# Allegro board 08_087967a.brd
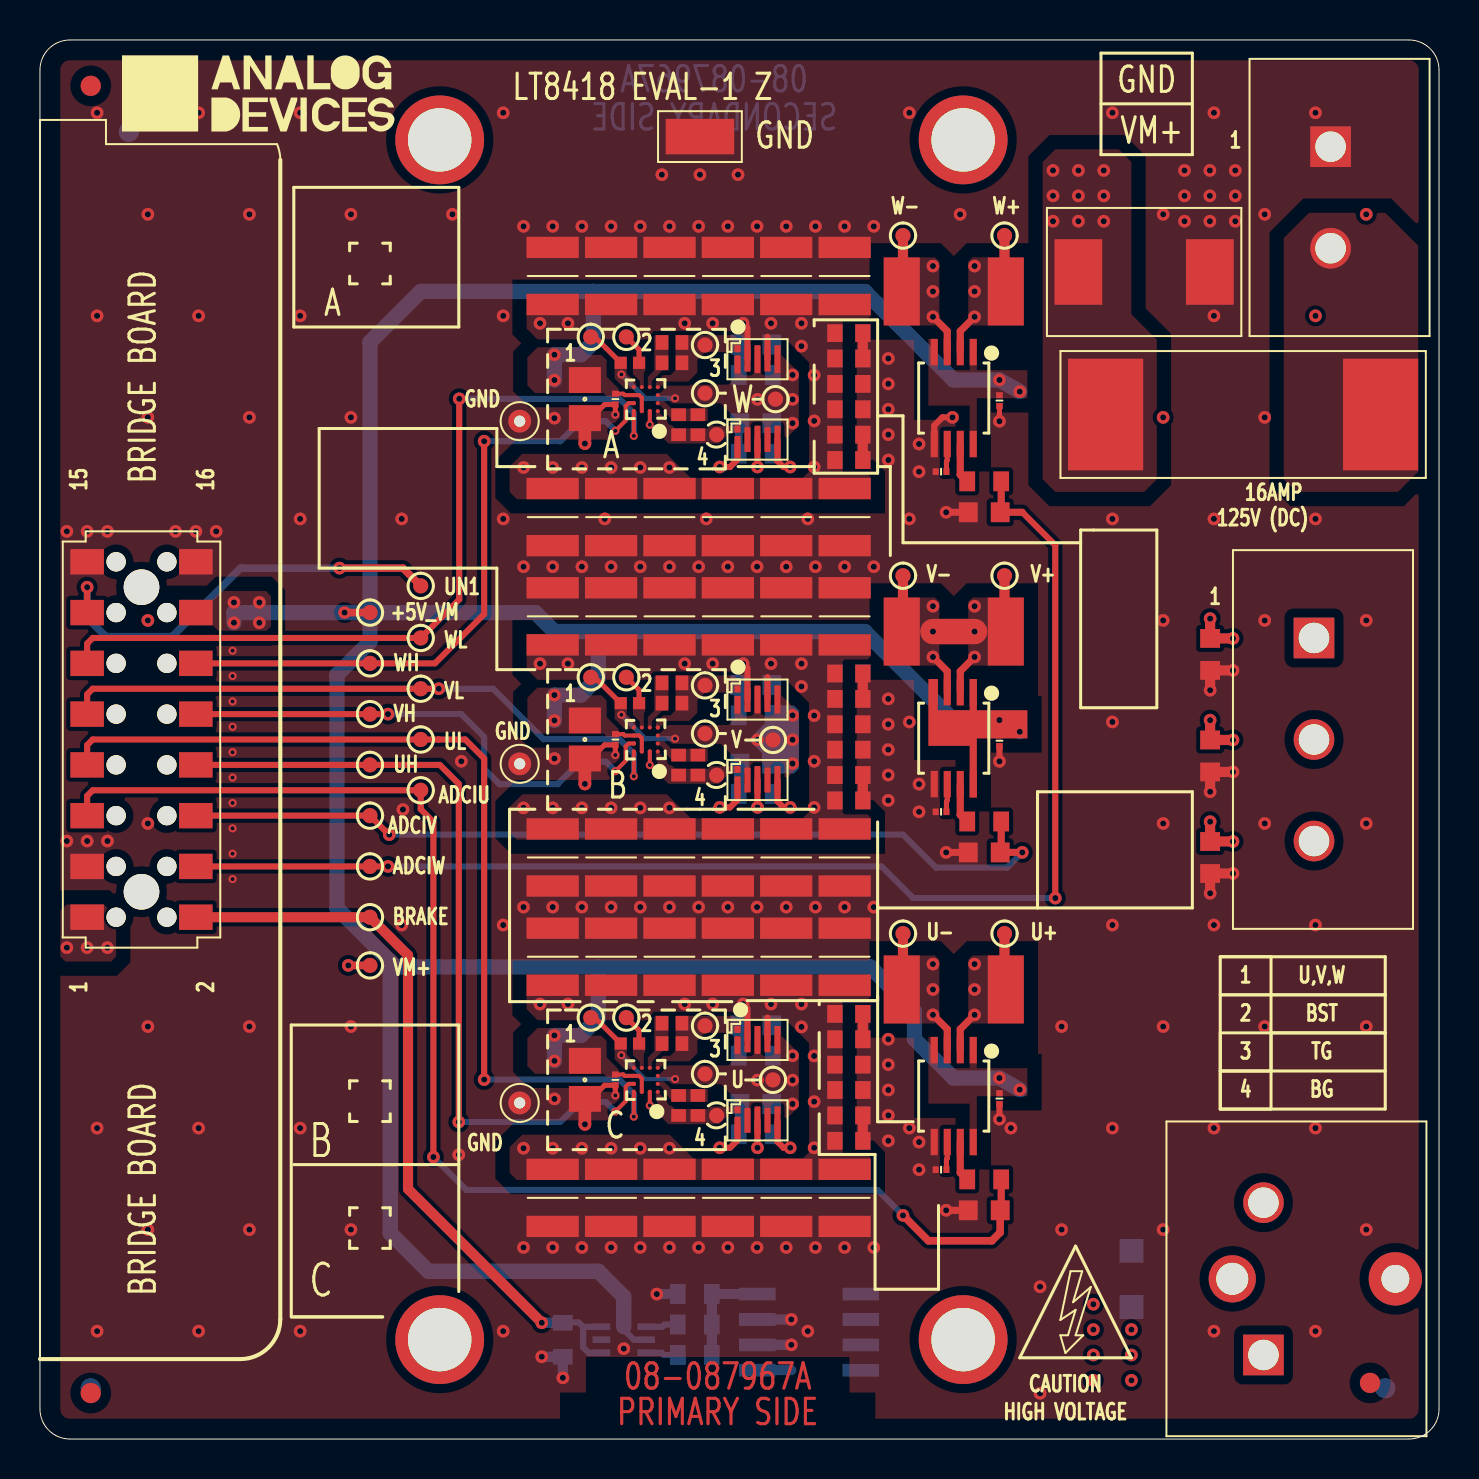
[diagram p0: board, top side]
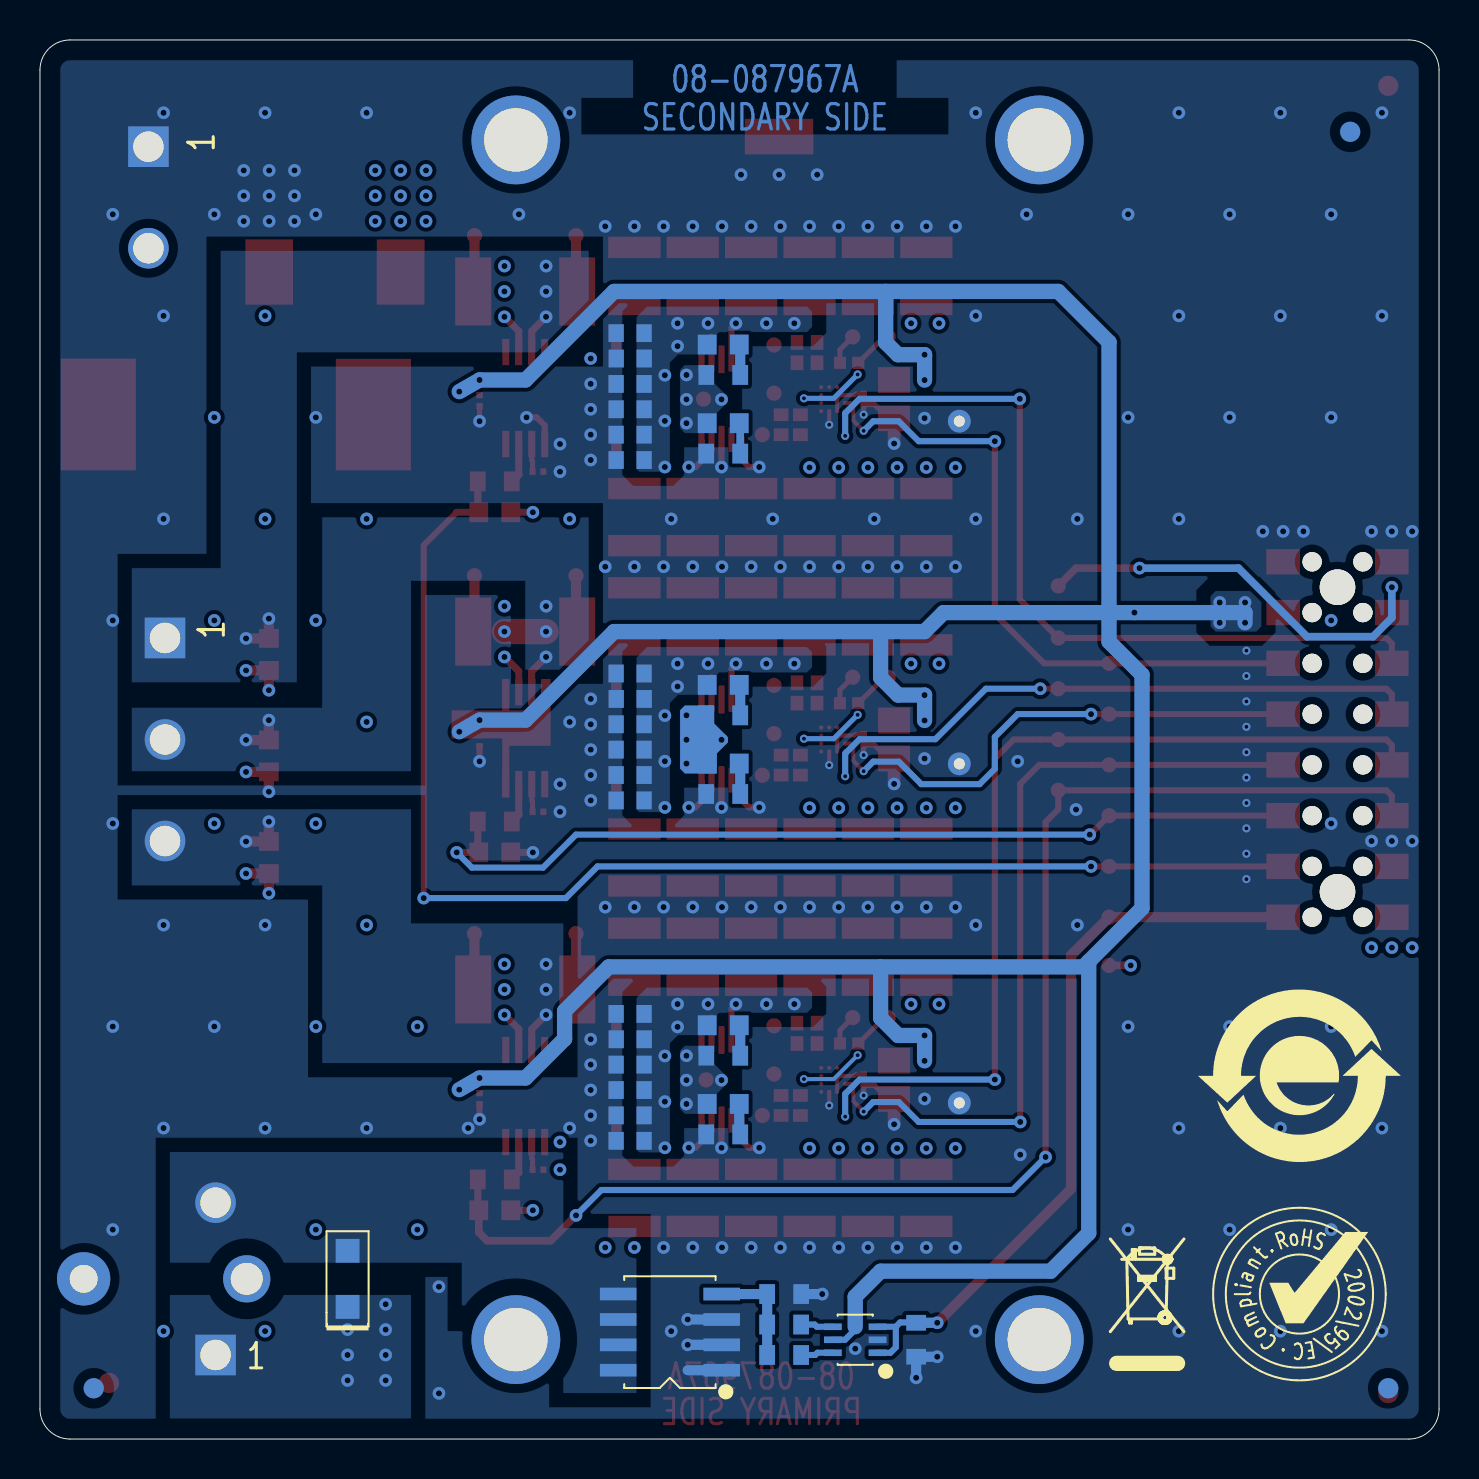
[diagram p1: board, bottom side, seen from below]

Outline 70 x 70 mm; copper layers: TOP, L2_GND, L3_SIG, BOTTOM. Coordinates in mm from the lower left corner of the outline.
Outline path: 0,68.5 arc(0.44,69.56) 1.5,70 68.5,70 arc(69.56,69.56) 70,68.5 70,1.5 arc(69.56,0.44) 68.5,0 1.5,0 arc(0.44,0.44) 0,1.5 0,68.5

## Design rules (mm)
constraint set DEFAULT: min track width 0.203
net group ADC_I_U: nets _N51 ADC_I_U
net group ADC_I_V: nets _N52 ADC_I_V
net group ADC_I_W: nets _N55 ADC_I_W
net group U: nets _N126 _N127
net group V: nets _N129 _N130
net group W: nets _N131 _N132
net group _N123: nets _N123 _N147 _N148

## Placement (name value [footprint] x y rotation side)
C1  4.7uF  [C1210H87]  28.57 58.19 90 top
C2  4.7uF  [C1210H87]  37.34 46.13 270 top
C3  4.7uF  [C0805H60]  27.26 35 90 top
C4  0.1uF  [C0201]  28.79 35 90 top
C5  0.1uF  [C0201]  28.79 52.03 90 top
C6  0.1uF  [C0402_B]  29.51 36.82 0 top
C7  0.1uF  [C0402_B]  29.51 19.79 0 top
C8  0.1uF  [C0402_B]  29.51 53.85 0 top
C9  0.1uF  [C0201]  45.09 13.48 180 top
C10  0.1uF  [C0201]  45.09 31.38 180 top
C11  0.1uF  [C0201]  45.09 48.4 180 top
C12  0.1uF  [C0201]  48.01 51.96 90 top
C13  0.1uF  [C0201]  48.01 34.94 90 top
C14  0.1uF  [C0201]  28.79 17.97 90 top
C15  4.7uF  [C0805H60]  27.26 17.97 90 top
C16  4.7uF  [C0805H60]  27.26 52.03 90 top
C17  0.1uF  [C0201]  48.01 17.03 90 top
C18  4.7uF  [C1210H87]  34.42 58.19 90 top
C19  4.7uF  [C1210H87]  37.34 58.19 90 top
C20  4.7uF  [C1210H87]  25.65 58.19 90 top
C21  4.7uF  [C1210H87]  34.42 46.13 270 top
C22  4.7uF  [C1210H87]  40.26 46.13 270 top
C23  4.7uF  [C1210H87]  28.57 46.13 270 top
C24  4.7uF  [C1210H87]  31.5 58.19 90 top
C25  4.7uF  [C1210H87]  31.5 46.13 270 top
C26  4.7uF  [C1210H87]  34.42 41.16 90 top
C27  4.7uF  [C1210H87]  40.26 29.1 270 top
C28  4.7uF  [C1210H87]  34.42 29.1 270 top
C29  4.7uF  [C1210H87]  31.5 41.16 90 top
C30  4.7uF  [C1210H87]  28.57 41.16 90 top
C31  4.7uF  [C1210H87]  28.57 29.1 270 top
C32  4.7uF  [C1210H87]  25.65 41.16 90 top
C33  4.7uF  [C1210H87]  25.65 29.1 270 top
C34  4.7uF  [C1210H87]  31.5 12.07 270 top
C35  4.7uF  [C1210H87]  28.57 12.07 270 top
C36  4.7uF  [C1210H87]  25.65 12.07 270 top
C37  4.7uF  [C1210H87]  37.34 24.13 90 top
C38  4.7uF  [C1210H87]  25.65 24.13 90 top
C39  4.7uF  [C1210H87]  40.26 24.13 90 top
C40  4.7uF  [C1210H87]  40.26 12.07 270 top
C41  4.7uF  [C1210H87]  34.42 12.07 270 top
C42  4.7uF  [C1210H87]  25.65 46.13 270 top
C43  4.7uF  [C1210H87]  40.26 41.16 90 top
C44  4.7uF  [C1210H87]  37.34 41.16 90 top
C45  4.7uF  [C1210H87]  37.34 29.1 270 top
C46  4.7uF  [C1210H87]  37.34 12.07 270 top
C47  4.7uF  [C1210H87]  34.42 24.13 90 top
C48  4.7uF  [C1210H87]  28.57 24.13 90 top
C49  4.7uF  [C1210H87]  31.5 29.1 270 top
C50  4.7uF  [C1210H87]  31.5 24.13 90 top
C51  4.7uF  [C1210H87]  40.26 58.19 90 top
C52  47NF  [C0603]  40.47 20 0 top
C53  47NF  [C0603]  40.47 17.46 0 top
C54  47NF  [C0603]  40.47 18.73 0 top
C55  47NF  [C0603]  40.47 21.27 0 top
C56  47NF  [C0603]  40.47 14.92 0 top
C57  47NF  [C0603]  40.47 16.19 0 top
C58  0.22UF  [C0603]  40.47 51.52 0 bottom
C59  0.22UF  [C0603]  40.47 52.79 0 bottom
C60  0.22UF  [C0603]  40.47 50.25 0 bottom
C61  0.22UF  [C0603]  40.47 48.98 0 bottom
C62  0.22UF  [C0603]  40.47 54.06 0 bottom
C63  0.22UF  [C0603]  40.47 55.33 0 bottom
C64  47NF  [C0603]  40.47 34.49 0 top
C65  47NF  [C0603]  40.47 35.76 0 top
C66  47NF  [C0603]  40.47 31.95 0 top
C67  47NF  [C0603]  40.47 37.03 0 top
C68  47NF  [C0603]  40.47 38.3 0 top
C69  47NF  [C0603]  40.47 33.22 0 top
C70  0.22UF  [C0603]  40.47 35.76 0 bottom
C71  0.22UF  [C0603]  40.47 38.3 0 bottom
C72  0.22UF  [C0603]  40.47 37.03 0 bottom
C73  0.22UF  [C0603]  40.47 34.49 0 bottom
C74  0.22UF  [C0603]  40.47 33.22 0 bottom
C75  0.22UF  [C0603]  40.47 31.95 0 bottom
C76  47NF  [C0603]  40.47 48.98 0 top
C77  47NF  [C0603]  40.47 55.33 0 top
C78  47NF  [C0603]  40.47 54.06 0 top
C79  47NF  [C0603]  40.47 52.79 0 top
C80  47NF  [C0603]  40.47 51.52 0 top
C81  47NF  [C0603]  40.47 50.25 0 top
C82  0.22UF  [C0603]  40.47 18.73 0 bottom
C83  0.22UF  [C0603]  40.47 21.27 0 bottom
C84  0.22UF  [C0603]  40.47 17.46 0 bottom
C85  0.22UF  [C0603]  40.47 16.19 0 bottom
C86  0.22UF  [C0603]  40.47 14.92 0 bottom
C87  0.22UF  [C0603]  40.47 20 0 bottom
C88  2200pF  [C0603#2]  47.24 46.37 180 top
C89  2200pF  [C0603#2]  47.24 29.35 180 top
C90  2200pF  [C0603#2]  47.24 11.44 180 top
C91  1000pF  [C0603#2]  58.55 29.1 270 top
C92  1000pF  [C0603#2]  58.55 34.18 270 top
C93  1000pF  [C0603#2]  58.55 39.26 270 top
C94  0.01uF  [C0603#2]  35.81 16.77 180 bottom
C95  0.01uF  [C0603#2]  35.81 20.7 180 bottom
C96  0.01uF  [C0603#2]  35.81 33.8 180 bottom
C97  0.01uF  [C0603#2]  35.81 37.73 180 bottom
C98  0.01uF  [C0603#2]  35.81 50.83 180 bottom
C99  0.01uF  [C0603#2]  35.81 54.76 180 bottom
D1  PMEG10020AELRX  [SOD123F]  54.61 8.01 90 bottom
D2  SMCJ58CA  [DO214AB_A]  55.24 58.39 180 top
F1  16A  [FSML606W211H211]  60.2 51.26 0 top
NOREF  -  [unnamed]  2.54 2.3 0 top
NOREF#2  -  [#2]  70 70 180 top
NOREF#3  -  [#2]  -69.85 -54.85 0 top
NOREF#4  -  [#2]  -69.85 -54.85 0 top
NOREF#5  -  [unnamed]  46.19 4.97 0 top
NOREF#6  -  [#2]  10.8 67.32 0 top
NOREF#7  -  [unnamed]  46.19 65 0 top
NOREF#8  -  [unnamed]  2.54 67.7 0 top
NOREF#9  -  [#2]  0 70 270 top
NOREF#10  -  [#2]  0 0 0 top
NOREF#11  -  [unnamed]  20 65 0 top
NOREF#12  -  [#2]  68.5 0 90 top
NOREF#13  -  [#2]  0 68.5 0 top
NOREF#14  -  [unnamed]  20 4.97 0 top
NOREF#15  -  [#2]  0 0 0 top
NOREF#16  -  [unnamed]  66.55 2.81 0 top
NOREF#17  -  [#2]  70 1.5 0 top
NOREF#18  -  [#2]  70 0 90 top
NOREF#19  -  [#2]  35 95.4 0 top
NOREF#20  -  [#2]  120.9 264.92 0 top
NOREF#21  -  [#2]  231.78 215.66 0 top
NOREF#22  -  [#2]  -69.85 -54.85 0 top
NOREF#23  -  [#2]  0 0 0 top
NOREF#24  -  [#2]  1.5 70 0 top
NOREF#25  -  [unnamed]  2.54 2.54 180 bottom
NOREF#26  -  [#2]  6.99 7.25 180 bottom
NOREF#27  -  [unnamed]  67.31 2.54 180 bottom
NOREF#28  -  [#2]  14.81 3.47 180 bottom
NOREF#29  -  [unnamed]  4.45 65.41 180 bottom
NOREF#30  -  [#2]  6.99 18.17 180 bottom
P1  1838210000  [CNWEIDMULLER1838210000]  64.57 64.66 270 top
P2  1907131  [CNPHOENIX1907131]  61.21 4.2 90 top
P3  HLE-108-02-F-DV-BE-A-K-TR  [CNSMFHDR2X8L800W200H154]  5.08 35 90 top
P4  1838220000  [CNWEIDMULLER1838220000]  63.74 40.08 270 top
Q1  EPC2204  [DIE6_2_5X1_5]  35.9 54.03 0 top
Q2  EPC2204  [DIE6_2_5X1_5]  35.9 50 0 top
Q3  EPC2204  [DIE6_2_5X1_5]  35.9 37 0 top
Q4  EPC2204  [DIE6_2_5X1_5]  35.9 32.97 0 top
Q5  EPC2204  [DIE6_2_5X1_5]  35.9 19.97 0 top
Q6  EPC2204  [DIE6_2_5X1_5]  35.9 15.94 0 top
Q7  SI4190ADY-T1-GE3  [SO8NB-5]  38.48 5.35 90 bottom
R1  0.001  [R2512H31_PAD71X134]  45.72 57.42 0 top
R2  0.001  [R2512H31_PAD71X134]  45.72 22.49 0 top
R3  0.001  [R2512H31_PAD71X134]  45.72 40.4 0 top
R4  5.6  [R0402]  31.62 19.79 0 top
R5  5.6  [R0402]  31.62 20.8 0 top
R6  5.6  [R0402]  32.92 16.69 270 top
R7  5.6  [R0402]  31.95 16.69 270 top
R8  5.6  [R0402]  31.95 33.72 270 top
R9  5.6  [R0402]  32.92 33.72 270 top
R13  5.6  [R0402]  31.62 36.82 0 top
R14  5.6  [R0402]  31.62 37.83 0 top
R15  5.6  [R0402]  31.95 50.75 270 top
R16  5.6  [R0402]  32.92 50.75 270 top
R17  5.6  [R0402]  31.62 54.86 0 top
R18  5.6  [R0402]  31.62 53.85 0 top
R19  10K  [R0603]  26.16 4.97 270 bottom
R20  50  [R0603]  35.81 15.24 0 bottom
R21  50  [R0603]  35.81 19.18 0 bottom
R22  50  [R0603]  35.81 32.27 0 bottom
R23  50  [R0603]  35.81 36.21 0 bottom
R24  50  [R0603]  35.81 49.3 0 bottom
R25  50  [R0603]  35.81 53.24 0 bottom
R26  1K  [R0603]  32.77 4.2 0 bottom
R27  1K  [R0603]  32.77 5.73 0 bottom
R28  10K  [R0603]  32.77 7.25 180 bottom
R29  1K  [R0603]  47.24 12.99 0 top
R30  1K  [R0603]  47.24 47.92 0 top
R31  1K  [R0603]  47.24 30.9 0 top
TP1  TESTPAD  [TPSMC30]  29.34 55.14 0 top
TP2  TESTPAD  [TPSMC30]  29.34 38.11 0 top
TP3  TESTPAD  [TPSMC30]  29.34 21.08 0 top
TP4  TESTPAD  [TPSMC30]  33.27 37.71 0 top
TP5  TESTPAD  [TPSMC30]  33.27 20.68 0 top
TP6  TESTPAD  [TPSMC30]  33.27 54.74 0 top
TP7  TESTPAD  [TPSMC30]  36.67 17.97 0 top
TP8  TESTPAD  [TPSMC30]  27.56 21.08 0 top
TP9  TESTPAD  [TPSMC30]  36.67 34.98 0 top
TP10  TESTPAD  [TPSMC30]  27.56 38.11 0 top
TP11  TESTPAD  [TPSMC30]  36.8 52.03 0 top
TP12  TESTPAD  [TPSMC30]  27.56 55.14 0 top
TP13  TESTPAD  [TPSMC30]  33.86 50.25 0 top
TP14  TESTPAD  [TPSMC30]  33.86 33.21 0 top
TP15  TESTPAD  [TPSMC30]  33.86 16.19 0 top
TP19  TESTPAD  [TPSMC30]  33.27 52.32 0 top
TP20  TESTPAD  [TPSMC30]  33.27 35.29 0 top
TP21  TESTPAD  [TPSMC30]  33.27 18.26 0 top
TP22  TESTPAD  [TPSMC30]  19.05 35 0 top
TP23  TESTPAD  [TPSMC30]  16.51 33.73 0 top
TP24  TESTPAD  [TPSMC30]  19.05 37.54 0 top
TP25  TESTPAD  [TPSMC30]  16.51 36.27 0 top
TP26  TESTPAD  [TPSMC30]  19.05 40.08 0 top
TP27  TESTPAD  [TPSMC30]  16.51 38.81 0 top
TP28  TESTPAD  [TPSMC30]  43.18 43.19 0 top
TP29  TESTPAD  [TPSMC30]  48.26 43.19 0 top
TP30  TESTPAD  [TPSMC30]  43.18 60.21 0 top
TP31  TESTPAD  [TPSMC30]  48.26 60.21 0 top
TP32  TESTPAD  [TPSMC30]  43.18 25.29 0 top
TP33  TESTPAD  [TPSMC30]  48.26 25.29 0 top
TP34  TESTPAD  [TPSMC30]  16.51 26.11 0 top
TP35  TESTPAD  [TPSMC30]  16.51 28.65 0 top
TP36  TESTPAD  [TPSMC30]  16.51 31.19 0 top
TP37  TESTPAD  [TPSMC30]  19.05 32.46 0 top
TP38  TESTPAD  [TPSMC30]  19.05 42.69 0 top
TP39  TESTPAD  [TPSMC30]  16.51 41.35 0 top
TP40  TESTPAD  [TPSMC30]  16.51 23.7 0 top
TP41  5015  [CNKEY5015TP]  33.02 65.16 0 top
U1  LT8418ACBZ-R7  [WLCSP16_12P_1_67X1_67H0_56]  30.31 52.03 180 top
U2  LT8418ACBZ-R7  [WLCSP16_12P_1_67X1_67H0_56]  30.31 35 180 top
U3  LT8418ACBZ-R7  [WLCSP16_12P_1_67X1_67H0_56]  30.31 17.97 180 top
U4  LT1999HMS8-50#PBF  [MSOP8]  45.72 35.07 180 top
U5  LT1999HMS8-50#PBF  [MSOP8]  45.72 17.16 180 top
U6  LT1999HMS8-50#PBF  [MSOP8]  45.72 52.08 180 top
U7  74LVC2G17GW,125  [SOT363]  29.21 4.97 90 bottom
W1  WP22  [TPC45D22]  24 50.93 0 top
W2  WP22  [TPC45D22]  24 33.78 0 top
W3  WP22  [TPC45D22]  24 16.82 0 top

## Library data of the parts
C1 C2 C18-C51 = CAP: User Part Number: UPN; Tolerance: 10; alternate symbols: (C1210L); tolerance: 10
C3 C15 C16 = CAP: Tolerance: 10; User Part Number: UPN; alternate symbols: (C0805H60); tolerance: 10
C4 C5 C9-C14 C17 = CAP: Tolerance: 10; User Part Number: UPN; alternate symbols: (C0201L); tolerance: 10
C6-C8 = CAP: Tolerance: 10; User Part Number: UPN; alternate symbols: (C0402_BL); tolerance: 10
C52-C87 = CAP: User Part Number: UPN; Tolerance: 10; alternate symbols: (C0603L); tolerance: 10
C88-C90 C94-C99 = CAP: User Part Number: UPN; Tolerance: 10; alternate symbols: (C0603); tolerance: 10
C91-C93 = CAP: User Part Number: UPN; Tolerance: 5; alternate symbols: (C0603); tolerance: 5
D1 = DIOSCHOTTKY: Tolerance: N/A; User Part Number: UPN; alternate symbols: (SOD123F); tolerance: N/A
D2 = DIOZNR_V2: User Part Number: UPN; Tolerance: N/A; alternate symbols: (DO214AB_A); tolerance: N/A
F1 = FSFUSE: Tolerance: N/A; User Part Number: UPN; alternate symbols: (FSML606W211H211); tolerance: N/A
P1 = CN2P: User Part Number: UPN; Tolerance: N/A; alternate symbols: (CNWEIDMULLER1838210000); tolerance: N/A
P2 = CN2P: User Part Number: UPN; Tolerance: N/A; alternate symbols: (CNPHOENIX1907131); tolerance: N/A
P3 = CN16P: User Part Number: UPN; Tolerance: N/A; alternate symbols: (CNSMFHDR2X8L800W200H154); tolerance: N/A
P4 = CN3P: User Part Number: UPN; Tolerance: N/A; alternate symbols: (CNWEIDMULLER1838220000); tolerance: N/A
Q1-Q6 = TRANNGANFET6P_V2: User Part Number: UPN; Tolerance: N/A; alternate symbols: (DIE6_2_5X1_5); tolerance: N/A
Q7 = TRANNMOSFET8P: Tolerance: N/A; User Part Number: UPN; alternate symbols: (SO8NB-5); tolerance: N/A
R1-R3 = RES: User Part Number: UPN; Tolerance: 1; alternate symbols: (R2512H31_PAD71X134); tolerance: 1
R4-R9 R13-R18 = RES: User Part Number: UPN; Tolerance: 1; alternate symbols: (R0402); tolerance: 1
R19 R26-R31 = RES: User Part Number: UPN; Tolerance: 1; alternate symbols: (R0603); tolerance: 1
R20-R25 = RES: User Part Number: UPN; Tolerance: 0.1; alternate symbols: (R0603); tolerance: 0.1
TP1-TP15 TP19-TP40 = NCTESTPAD: Tolerance: N/A; User Part Number: UPN; alternate symbols: (TPSMC30); tolerance: N/A
TP41 = CNTP1P: Tolerance: N/A; User Part Number: UPN; alternate symbols: (CNKEY5015TP); tolerance: N/A
U1-U3 = ADLT8418: User Part Number: UPN; Tolerance: N/A; alternate symbols: (WLCSP16_12P_1_67X1_67H0_56); tolerance: N/A
U4-U6 = ADLT1999: Tolerance: N/A; User Part Number: UPN; alternate symbols: (MSOP8); tolerance: N/A
U7 = 74217: User Part Number: UPN; Tolerance: N/A; alternate symbols: (SOT363); tolerance: N/A
W1-W3 = NCWP: User Part Number: UPN; Tolerance: N/A; alternate symbols: (TPC45D22); tolerance: N/A

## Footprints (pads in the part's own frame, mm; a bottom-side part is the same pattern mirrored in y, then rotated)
C0201
  rect 0.305x0.33 smd: 1(-0.27,0) 2(0.27,0)
C0402_B
  rect 0.61x0.61 smd: 1(-0.46,0) 2(0.46,0)
C0603
  rect 0.762x0.889 smd: 1(-0.7,0) 2(0.7,0)
C0603#2
  rect 0.94x0.991 smd: 1(-0.8,0) 2(0.8,0)
C0805H60
  rect 1.295x1.6 smd: 1(-0.953,0) 2(0.953,0)
C1210H87
  rect 1.067x2.616 smd: 1(-1.428,0) 2(1.428,0)
CNKEY5015TP
  rect 3.429x1.778 smd: 1(0,0)
CNPHOENIX1907131
  round 2.362 hole 1.6 unplated: (3.81,1.56)
  round 2.667 hole 1.397 unplated: (3.81,-6.6)
  rect 2.032x2.032 hole 1.524: 1(0,0)
  round 2.032 hole 1.524: 2(7.62,0)
CNSMFHDR2X8L800W200H154
  round 0.965 hole 0.965 unplated: (-8.89,1.27) (-8.89,-1.27) (-6.35,1.27) (-6.35,-1.27) (-3.81,1.27) (-3.81,-1.27) (-1.27,1.27) (-1.27,-1.27) (1.27,1.27) (1.27,-1.27) (3.81,1.27) (3.81,-1.27) (6.35,1.27) (6.35,-1.27) (8.89,1.27) (8.89,-1.27)
  round 1.778 hole 1.778 unplated: (-7.62,0) (7.62,0)
  rect 1.27x1.676 smd: 1(-8.89,2.72) 2(-8.89,-2.72) 3(-6.35,2.72) 4(-6.35,-2.72) 5(-3.81,2.72) 6(-3.81,-2.72) 7(-1.27,2.72) 8(-1.27,-2.72) 9(1.27,2.72) 10(1.27,-2.72) 11(3.81,2.72) 12(3.81,-2.72) 13(6.35,2.72) 14(6.35,-2.72) 15(8.89,2.72) 16(8.89,-2.72)
CNWEIDMULLER1838210000
  rect 2.032x2.032 hole 1.524: 1(0,0)
  round 2.032 hole 1.524: 2(5.08,0)
CNWEIDMULLER1838220000
  rect 2.032x2.032 hole 1.524: 1(0,0)
  round 2.032 hole 1.524: 2(5.08,0) 3(10.16,0)
DIE6_2_5X1_5
  rrect 0.305x0.356 smd: 1(-1,0.525)
  rrect 0.305x0.889 smd: 2(-1,-0.262)
  rrect 0.305x1.245 smd: 3(-0.5,0) 5(0.5,0)
  rrect 0.305x1.397 smd: 4(0,0) 6(1,0)
DO214AB_A
  rect 2.388x3.277 smd: 1(-3.289,0) 2(3.289,0)
FSML606W211H211
  rect 3.759x5.588 smd: 1(-6.88,0) 2(6.88,0)
MSOP8
  rect 0.356x1.321 smd: 1(-0.975,-2.3) 2(-0.325,-2.3) 3(0.325,-2.3) 4(0.975,-2.3) 5(0.975,2.3) 6(0.325,2.3) 7(-0.325,2.3) 8(-0.975,2.3)
R0402
  rect 0.635x0.737 smd: 1(-0.5,0) 2(0.5,0)
R0603
  rect 0.787x0.991 smd: 1(-0.85,0) 2(0.85,0)
R2512H31_PAD71X134
  rect 1.803x3.404 smd: 1(-2.602,0) 2(2.602,0)
SO8NB-5
  rect 0.635x1.829 smd: 1(-1.905,-2.591) 2(-0.635,-2.591) 3(0.635,-2.591) 4(1.905,-2.591) 5(1.905,2.591) 6(0.635,2.591) 7(-0.635,2.591) 8(-1.905,2.591)
SOD123F
  rect 1.194x1.194 smd: A(1.403,0) C(-1.403,0)
SOT363
  rect 0.33x0.889 smd: 1(-0.65,-1.118) 2(0,-1.118) 3(0.65,-1.118) 4(0.65,1.118) 5(0,1.118) 6(-0.65,1.118)
TPC45D22
  round 1.143 hole 0.559: 1(0,0)
TPSMC30
  round 0.762 smd: 1(0,0)
unnamed
  round 1.016 smd: (0,0)
WLCSP16_12P_1_67X1_67H0_56
  round 0.203 smd: A1(-0.6,0.6) A2(-0.2,0.6) A3(0.2,0.6) A4(0.6,0.6) B1(-0.6,0.2) B4(0.6,0.2) C1(-0.6,-0.2) C4(0.6,-0.2) D1(-0.6,-0.6) D2(-0.2,-0.6) D3(0.2,-0.6) D4(0.6,-0.6)

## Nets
+5V_VM: C3.2(N2) C4.2(N2) C5.2(N2) C12.2(N2) C13.2(N2) C14.2(N2) C15.2(N2) C16.2(N2) C17.2(N2) P3.14 TP39.1(N1) U1.A3 U1.C4(VCC_2) U2.A3 U2.C4(VCC_2) U3.A3 U3.C4(VCC_2) U4.1 U4.4(V+_2) U4.8 U5.1 U5.4(V+_2) U5.8 U6.1 U6.4(V+_2) U6.8 U7.5(VCC)
GND: C1.2(N2) C2.2(N2) C3.1 C4.1 C5.1 C9.2(N2) C10.2(N2) C11.2(N2) C12.1 C13.1 C14.1 C15.1 C16.1 C17.1 C18.2(N2) C19.2(N2) C20.2(N2) C21.2(N2) C22.2(N2) C23.2(N2) C24.2(N2) C25.2(N2) C26.2(N2) C27.2(N2) C28.2(N2) C29.2(N2) C30.2(N2) C31.2(N2) C32.2(N2) C33.2(N2) C34.2(N2) C35.2(N2) C36.2(N2) C37.2(N2) C38.2(N2) C39.2(N2) C40.2(N2) C41.2(N2) C42.2(N2) C43.2(N2) C44.2(N2) C45.2(N2) C46.2(N2) C47.2(N2) C48.2(N2) C49.2(N2) C50.2(N2) C51.2(N2) C52.2(N2) C53.2(N2) C54.2(N2) C55.2(N2) C56.2(N2) C57.2(N2) C58.2(N2) C59.2(N2) C60.2(N2) C61.2(N2) C62.2(N2) C63.2(N2) C64.2(N2) C65.2(N2) C66.2(N2) C67.2(N2) C68.2(N2) C69.2(N2) C70.2(N2) C71.2(N2) C72.2(N2) C73.2(N2) C74.2(N2) C75.2(N2) C76.2(N2) C77.2(N2) C78.2(N2) C79.2(N2) C80.2(N2) C81.2(N2) C82.2(N2) C83.2(N2) C84.2(N2) C85.2(N2) C86.2(N2) C87.2(N2) C88.2(N2) C89.2(N2) C90.2(N2) C91.2(N2) C92.2(N2) C93.2(N2) D2.1 P1.1 P3.3 P3.15 P3.16 Q2.2 Q2.4 Q2.6(S3) Q4.2 Q4.4 Q4.6(S3) Q6.2 Q6.4 Q6.6(S3) Q7.1 Q7.2 Q7.3(S3) R19.2(N2) R20.2(N2) R22.2(N2) R24.2(N2) R28.2(N2) TP41.1(N1) U1.A2 U2.A2 U3.A2 U4.5 U5.5 U6.5 U7.2 W1.1(N1) W2.1(N1) W3.1(N1)
_N13: C8.1 C98.1 Q1.2 Q1.4 Q1.6(S3) Q2.3 Q2.5 R1.2(N2) R25.2(N2) TP11.1(N1) TP12.1(N1) TP19.1(N1) TP31.1(N1) U1.C1 U1.D4 U6.2
_N42: Q1.1 R17.2(N2) R18.2(N2) TP6.1(N1) U1.D1
_N43: Q2.1 R15.2(N2) R16.2(N2) TP13.1(N1) U1.A1
_N44: Q3.1 R13.2(N2) R14.2(N2) TP4.1(N1) U2.D1
_N45: Q4.1 R8.2(N2) R9.2(N2) TP14.1(N1) U2.A1
_N46: Q5.1 R4.2(N2) R5.2(N2) TP5.1(N1) U3.D1
_N47: Q6.1 R6.2(N2) R7.2(N2) TP15.1(N1) U3.A1
_N48: R17.1 R18.1 U1.D2
_N49: R13.1 R14.1 U2.D2
_N50: R4.1 R5.1 U3.D2
_N51: R29.1 U5.7
_N52: R31.1 U4.7
_N55: R30.1 U6.7
_N68: R15.1 R16.1 U1.B1
_N70: R6.1 R7.1 U3.B1
_N71: R8.1 R9.1 U2.B1
_N83: C6.2(N2) TP2.1(N1) U2.D3
_N84: C7.2(N2) TP3.1(N1) U3.D3
_N85: C8.2(N2) TP1.1(N1) U1.D3
_N109: C10.1 U4.6
_N110: C9.1 U5.6
_N111: C11.1 U6.6
_N123: Q7.4 R26.2(N2) R27.2(N2) R28.1
_N126: C94.2(N2) R20.1
_N127: C95.2(N2) R21.1
_N129: C97.2(N2) R23.1
_N130: C96.2(N2) R22.1
_N131: C98.2(N2) R24.1
_N132: C99.2(N2) R25.1
_N135: D1.A(P) P2.2(N2) Q7.5 Q7.6 Q7.7 Q7.8
_N140: F1.2(N2) P1.2(N2)
_N147: R27.1 U7.4
_N148: R26.1 U7.6
ADC_I_U: C90.1 P3.5 R29.2(N2) TP37.1(N1)
ADC_I_V: C89.1 P3.6 R31.2(N2) TP36.1(N1)
ADC_I_W: C88.1 P3.4 R30.2(N2) TP35.1(N1)
BRAKE: P3.2 R19.1 TP34.1(N1) U7.1 U7.3
U: C91.1 P4.3(N3) R2.1 TP32.1(N1) U5.3
U_X: C7.1 C94.1 Q5.2 Q5.4 Q5.6(S3) Q6.3 Q6.5 R2.2(N2) R21.2(N2) TP7.1(N1) TP8.1(N1) TP21.1(N1) TP33.1(N1) U3.C1 U3.D4 U5.2
UH: P3.8 TP23.1(N1) U3.B4
UL: P3.7 TP22.1(N1) U3.A4
UN1: P3.13 TP38.1(N1)
V: C6.1 C92.1 C96.1 P4.2 Q3.2 Q3.4 Q3.6(S3) Q4.3 Q4.5 R3.1 R3.2(N2) R23.2(N2) TP9.1(N1) TP10.1(N1) TP20.1(N1) TP28.1(N1) TP29.1(N1) U2.C1 U2.D4 U4.2 U4.3
VH: P3.10 TP25.1(N1) U2.B4
VL: P3.9(N9) TP24.1(N1) U2.A4
VM+: C1.1 C2.1 C18.1 C19.1 C20.1 C21.1 C22.1 C23.1 C24.1 C25.1 C26.1 C27.1 C28.1 C29.1 C30.1 C31.1 C32.1 C33.1 C34.1 C35.1 C36.1 C37.1 C38.1 C39.1 C40.1 C41.1 C42.1 C43.1 C44.1 C45.1 C46.1 C47.1 C48.1 C49.1 C50.1 C51.1 C52.1 C53.1 C54.1 C55.1 C56.1 C57.1 C58.1 C59.1 C60.1 C61.1 C62.1 C63.1 C64.1 C65.1 C66.1 C67.1 C68.1 C69.1 C70.1 C71.1 C72.1 C73.1 C74.1 C75.1 C76.1 C77.1 C78.1 C79.1 C80.1 C81.1 C82.1 C83.1 C84.1 C85.1 C86.1 C87.1 C95.1 C97.1 C99.1 D1.C D2.2(N2) F1.1 P2.1 P3.1 Q1.3 Q1.5 Q3.3 Q3.5 Q5.3 Q5.5 TP40.1(N1)
W: C93.1 P4.1 R1.1 TP30.1(N1) U6.3
WH: P3.12 TP27.1(N1) U1.B4
WL: P3.11 TP26.1(N1) U1.A4

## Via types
v1: diameter 0.635, hole 0.305, TOP to BOTTOM, 352 vias
v2: diameter 0.406, hole 0.203, TOP to BOTTOM, 28 vias

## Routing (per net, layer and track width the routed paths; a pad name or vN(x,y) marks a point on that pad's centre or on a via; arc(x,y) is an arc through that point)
+5V_VM: length 201
  TOP w0.203: U1.A3 30.11,52.1 29.98,52.23 U1.C4 29.26,52.23 29.19,52.3 C5.2 ; C4.2 29.19,35.27 29.26,35.2 U2.C4 29.98,35.2 30.11,35.07 U2.A3 ; C14.2 29.19,18.24 29.26,18.17 U3.C4 29.98,18.17 30.11,18.04 U3.A3
  TOP w0.381: TP39.1 v1(15.24,41.35)
  BOTTOM w0.305: U7.5 29.72,4.97 29.21,5.47 29.21,5.62
  BOTTOM w0.762: 27.94,40.4 25.74,40.4 24.79,41.35 TP39.1 ; 27.94,40.4 41.27,40.4 45.7,35.97 v1(48.01,35.97) v1(49.02,35.39) ; 27.94,40.4 27.94,38.1 27.06,37.22 v1(25.74,37.22) v1(25.74,35.95) ; 27.69,57.42 41.27,57.42 45.7,52.99 v1(48.01,52.99) v1(49.02,52.4) ; 27.69,57.42 19.05,57.42 16.51,54.88 TP39.1 ; 27.69,57.42 27.69,54.86 27.07,54.25 v1(25.74,54.25) v1(25.74,52.98) ; 17.53,23.89 17.53,10.3 19.43,8.4 27.94,8.4 29.21,7.13 29.21,5.62 ; 17.53,23.89 14.86,26.56 14.86,38.24 16.51,39.89 TP39.1 ; 17.53,23.89 17.79,23.62 27.94,23.62 ; v1(49.02,17.48) v1(48.01,18.06) 45.7,18.06 43.75,20.02 43.75,21.41 41.54,23.62 27.94,23.62 ; TP39.1 v1(15.24,41.35) 9.71,41.35 v1(9.71,40.84) ; 27.94,23.62 27.94,21.07 27.06,20.19 v1(25.74,20.19) v1(25.74,18.92)
  vias: v1(9.71,41.86) v1(10.98,41.86) v1(10.98,40.84)
GND: length 57.6
  TOP w0.203: U3.A2 v2(30.51,16.69) ; U2.A2 v2(30.51,33.72) ; U1.A2 v2(30.51,50.75)
  TOP w0.254: v2(28.79,17.19) C14.1 28.25,17.7 27.57,17.02 C15.1 ; C3.1 27.57,34.05 28.25,34.73 C4.1 v2(28.79,34.22) ; v2(28.79,51.25) C5.1 28.25,51.76 27.57,51.08 C16.1 ; C12.1 v1(48.01,50.92)
  TOP w0.305: Q6.2 34.9,14.95 34.52,14.57 v1(34.01,14.57) ; Q4.6 36.9,31.91 37.2,31.6 v1(37.54,31.6) ; C13.1 v1(48.01,33.91) ; Q2.4 v1(35.9,48.63) ; U6.5 44.74,50.71 45.15,51.12 v1(45.66,51.12) ; Q2.6 36.9,48.94 37.2,48.63 v1(37.54,48.63) ; Q6.4 v1(35.9,14.57) ; Q6.6 36.9,14.88 37.2,14.57 v1(37.54,14.57) ; v1(34.01,48.63) 34.52,48.63 34.9,49.01 Q2.2 ; Q4.4 v1(35.9,31.6) ; Q4.2 34.9,31.98 34.52,31.6 v1(34.01,31.6) ; C17.1 v1(48.01,16)
  TOP w0.356: C90.2 v1(45.34,11.44) ; C88.2 v1(45.34,46.37) ; C89.2 v1(45.34,29.35)
  TOP w0.508: v1(59.69,33.38) C92.2 v1(58.55,32.39) ; C76.2 C81.2 ; C56.2 C57.2 ; v1(58.55,37.47) C93.2 v1(59.69,38.46) ; v1(59.69,28.3) C91.2 v1(58.55,27.31) ; C66.2 C69.2 ; C77.2 C78.2 ; C68.2 C67.2 ; C55.2 C52.2
  TOP w0.635: v1(27.26,49.81) C16.1 ; v1(27.26,15.75) C15.1 ; v1(27.26,32.78) C3.1
  BOTTOM w0.508: Q7.2 v1(37.59,4.71) ; Q7.1 37.59,3.44 ; R28.2 v1(30.86,7.25) ; Q7.3 v1(37.59,5.98) ; v1(26.16,3.06) R19.2 v1(25.11,4.12)
  vias: v1(1.34,45.41) v1(1.34,29.92) v1(2.36,45.41) v1(2.36,29.92) v1(2.86,66.36) v1(2.86,56.2) v1(2.86,15.56) v1(2.86,5.4) v1(3.38,45.41) v1(3.38,29.92) v1(5.4,61.28) v1(5.4,51.12) v1(5.4,40.96) v1(5.4,30.8) v1(5.4,20.64) v1(5.4,10.48) v1(6.78,45.41) v1(7.8,45.41) v1(7.94,66.36) v1(7.94,56.2) v1(7.94,15.56) v1(7.94,5.4) v1(8.82,45.41) v1(10.48,61.28) v1(10.48,51.12) v1(10.48,20.64) v1(10.48,10.48) v1(13.02,66.36) v1(13.02,56.2) v1(13.02,46.04) v1(13.02,15.56) v1(13.02,5.4) v1(15.56,61.28) v1(15.56,51.12) v1(15.56,20.64) v1(15.56,10.48) v1(18.1,46.04) v1(18.1,25.72) v1(18.16,31.5) v1(20.64,61.28) v1(20.95,14.22) v1(21.08,33.91) v1(23.18,66.36) v1(23.18,56.2) v1(23.18,46.04) v1(23.18,25.72) v1(23.18,5.4) v1(24.19,60.67) v1(24.19,43.64) v1(24.19,26.61) v1(24.19,9.58) v1(25.65,60.67) v1(25.74,51.08) v1(25.65,43.64) v1(25.74,34.05) v1(25.65,26.61) v1(25.74,17.02) v1(25.65,9.58) v1(27.11,60.67) v1(27.11,43.64) v1(27.11,26.61) v1(27.11,9.58) v1(28.26,46.04) v1(28.57,60.67) v1(28.57,43.64) v1(28.57,26.61) v1(28.57,9.58) v1(29.21,4.52) v1(30.04,60.67) v1(30.04,43.64) v1(30.04,26.61) v1(30.04,9.58) v1(31.11,63.26) v1(31.5,60.67) v1(31.5,43.64) v1(31.5,26.61) v1(31.5,9.58) v1(33.02,63.26) v1(32.96,60.67) v1(32.96,43.64) v1(32.96,26.61) v1(32.96,9.58) v1(33.34,46.04) v1(34.42,60.67) v1(34.42,43.64) v1(34.42,26.61) v1(34.42,9.58) v1(34.92,63.26) v1(35.88,60.67) v1(35.88,43.64) v1(35.88,26.61) v1(35.88,9.58) v1(37.34,60.67) v1(37.34,43.64) v1(37.34,26.61) v1(37.34,9.58) v1(38.42,46.04) v1(38.42,5.4) v1(38.8,60.67) v1(38.8,43.64) v1(38.8,26.61) v1(38.8,9.58) v1(40.26,60.67) v1(40.26,43.64) v1(40.26,26.61) v1(40.26,9.58) v1(41.72,60.67) v1(41.72,43.64) v1(41.72,26.61) v1(41.72,9.58) v1(42.45,54.06) v1(42.45,52.79) v1(42.45,51.52) v1(42.45,50.25) v1(42.45,48.98) v1(42.44,37.03) v1(42.44,35.76) v1(42.44,34.49) v1(42.44,33.22) v1(42.44,31.95) v1(42.45,20) v1(42.45,18.73) v1(42.45,17.46) v1(42.45,16.19) v1(42.45,14.92) v1(43.5,66.36) v1(43.5,46.04) v1(43.5,35.88) v1(43.5,15.56) v1(43.98,49.78) v1(43.98,48.4) v1(43.98,32.77) v1(43.98,31.38) v1(43.98,14.86) v1(43.98,13.48) v1(46.04,61.28) v1(48.58,15.56) v1(50.04,7.62) v1(50.04,2.29) v1(51.12,20.64) v1(51.12,10.48) v1(53.66,66.36) v1(53.66,46.04) v1(53.66,35.88) v1(53.66,25.72) v1(53.66,15.56) v1(56.2,61.28) v1(56.2,51.12) v1(56.2,40.96) v1(56.2,30.8) v1(56.2,20.64) v1(56.2,10.48) v1(57.26,63.47) v1(57.26,62.2) v1(57.26,60.93) v1(58.53,63.47) v1(58.53,62.2) v1(58.53,60.93) v1(58.74,66.36) v1(58.74,56.2) v1(58.74,46.04) v1(58.74,25.72) v1(58.74,15.56) v1(58.74,5.4) v1(59.8,63.47) v1(59.8,62.2) v1(59.8,60.93) v1(61.28,61.28) v1(61.28,51.12) v1(61.28,40.96) v1(61.28,30.8) v1(61.28,20.64) v1(63.82,66.36) v1(63.82,56.2) v1(63.82,46.04) v1(63.82,25.72) v1(63.82,15.56) v1(63.82,5.4) v1(66.36,61.28) v1(66.36,40.96) v1(66.36,30.8) v1(66.36,20.64) v1(66.36,10.48) v2(9.64,39.45) v2(9.64,38.18) v2(9.64,36.91) v2(9.64,35.64) v2(9.64,34.37) v2(9.64,33.1) v2(9.64,31.83) v2(9.64,30.56) v2(9.64,29.29) v2(9.64,28.02)
_N13: length 10.1
  TOP w0.254: TP12.1 27.76,55.14 C8.1
  TOP w0.356: v1(46.76,56.15) 46.05,55.43 U6.2
  TOP w0.508: R1.2 48.26,57.48 TP31.1
  BOTTOM w0.254: v2(29.09,53.27) 30.28,52.07 v2(31.78,52.07)
  vias: v1(35.9,52.02) v1(37.65,53.24) v1(37.65,52.02) v1(37.65,50.83) v1(46.76,58.69) v1(46.76,57.42)
_N44: length 0
_N51: length 2.5
  TOP w0.356: 46.05,13.34 46.05,13.32 46.39,12.97 ; 46.05,13.34 U5.7 ; 46.05,13.34 R29.1
_N52: length 2.5
  TOP w0.356: 46.05,31.25 46.05,31.22 46.39,30.87 ; 46.05,31.25 R31.1 ; 46.05,31.25 U4.7
_N55: length 2.5
  TOP w0.356: 46.05,48.27 46.05,48.24 46.39,47.89 ; 46.05,48.27 R30.1 ; 46.05,48.27 U6.7
_N83: length 1.6
  TOP w0.254: TP2.1 29.97,37.48 C6.2
_N84: length 1.6
  TOP w0.254: TP3.1 29.97,20.45 C7.2
_N85: length 1.6
  TOP w0.254: TP1.1 29.97,54.51 C8.2
_N109: length 1.4
  TOP w0.254: C10.1 45.36,31.91 45.39,31.95 U4.6
_N110: length 1.4
  TOP w0.254: C9.1 45.36,14 45.39,14.04 U5.6
_N111: length 1.4
  TOP w0.254: U6.6 45.39,48.96 45.36,48.92 C11.1
_N123: length 5.3
  BOTTOM w0.508: R26.2 R27.2 R28.1 Q7.4
_N126: length 1.5
  BOTTOM w0.508: C94.2 35.01,15.29 R20.1
_N127: length 1.5
  BOTTOM w0.508: R21.1 34.96,20.65 C95.2
_N129: length 1.5
  BOTTOM w0.508: C97.2 34.96,37.68 R23.1
_N130: length 1.5
  BOTTOM w0.508: R22.1 34.96,33.75 C96.2
_N131: length 1.5
  BOTTOM w0.381: C98.2 34.96,50.78 R24.1
_N132: length 1.5
  BOTTOM w0.508: C99.2 34.96,54.71 R25.1
_N147: length 1.6
  BOTTOM w0.305: U7.4 31.13,5.62 31.24,5.73 R27.1
_N148: length 1.6
  BOTTOM w0.305: U7.6 31.1,4.32 31.21,4.2 R26.1
ADC_I_U: length 69.3
  TOP w0.305: P3.5 2.36,32.18 2.64,32.46 TP37.1 19.05,31.51 19.68,30.87 v1(19.68,14.11)
  TOP w0.356: C90.1 48.09,11.49 R29.2
  TOP w0.381: v1(43.18,11.19) 44.45,9.92 47.62,9.92 48.04,10.34 C90.1
  BOTTOM w0.305: v1(19.68,14.11) 21.34,12.46 41.91,12.46 v1(43.18,11.19)
ADC_I_V: length 45.4
  TOP w0.305: P3.6 TP36.1 17.46,30.24 v1(17.48,30.24)
  TOP w0.356: R31.2 48.09,29.4 C89.1 v1(49.15,29.35)
  BOTTOM w0.305: v1(17.48,30.24) 43.18,30.24 44.83,28.59 48.39,28.59 v1(49.15,29.35)
ADC_I_W: length 66.3
  TOP w0.305: P3.4 TP35.1 v1(17.41,28.65) ; 49.15,46.37 50.8,44.72 v1(50.8,27.06)
  TOP w0.356: R30.2 48.09,46.42 C88.1 49.15,46.37
  BOTTOM w0.305: v1(50.8,27.06) 43.69,27.06 42.1,28.65 v1(17.41,28.65)
BRAKE: length 37.7
  TOP w0.508: v1(25.11,5.82) 18.41,12.51 18.41,24.21 TP34.1 P3.2
  BOTTOM w0.305: U7.3 27.18,5.62 ; 27.18,5.62 26.96,5.83 26.18,5.83 R19.1 ; 27.18,5.62 27.18,4.59 27.45,4.32 U7.1
  BOTTOM w0.508: R19.1 v1(25.11,5.82)
U: length 7
  TOP w0.356: v1(44.68,21.22) 45.39,20.51 U5.3
  TOP w0.508: TP32.1 43.18,22.55 R2.1 ; v1(59.69,29.9) C91.1 v1(58.55,30.89)
  vias: v1(44.68,23.76) v1(44.68,22.49)
U_X: length 10.1
  TOP w0.254: C7.1 27.76,21.08 TP8.1
  TOP w0.356: U5.2 46.05,20.51 v1(46.76,21.22)
  TOP w0.508: TP33.1 48.26,22.55 R2.2
  BOTTOM w0.203: v2(31.78,18.01) 30.28,18.01 v2(29.09,19.2)
  vias: v1(35.9,17.96) v1(37.65,19.18) v1(37.65,17.96) v1(37.65,16.77) v1(46.76,23.76) v1(46.76,22.49)
UH: length 40.8
  TOP w0.203: v2(28.79,16.38) 29.31,16.9 29.31,17.63 29.45,17.77 U3.B4
  TOP w0.305: v1(20.95,15.86) 20.95,32.78 20,33.73 17.41,33.73 TP23.1 P3.8
  BOTTOM w0.305: v1(20.95,15.86) 26.04,15.86 27.03,16.86 28.31,16.86 v2(28.79,16.38)
UL: length 47.6
  TOP w0.203: U3.A4 v2(29.71,16.13)
  TOP w0.305: P3.7 2.36,34.72 2.64,35 TP22.1 19.95,35 21.27,35 22.23,34.05 v1(22.23,17.99)
  BOTTOM w0.305: v1(22.23,17.99) 28.99,17.99 29.71,17.27 v2(29.71,16.13)
UN1: length 21.7
  TOP w0.305: P3.13 v1(2.36,42.62)
  TOP w0.381: TP38.1 18.16,43.57 v1(14.99,43.57)
  BOTTOM w0.381: v1(14.99,43.57) 10.03,43.57 6.6,40.15 3.3,40.15 2.36,41.09 v1(2.36,42.62)
V: length 19.2
  TOP w0.254: C6.1 27.76,38.11 TP10.1
  TOP w0.356: v1(46.76,39.13) 46.05,38.41 U4.2 ; v1(44.68,39.13) 45.39,38.41 U4.3
  TOP w0.508: TP28.1 43.18,40.46 R3.1 ; TP29.1 48.26,40.46 R3.2 ; v1(59.69,34.98) C92.1 v1(58.55,35.97)
  TOP w1.27: v1(44.68,40.4) v1(46.76,40.4)
  BOTTOM w0.254: v2(31.78,35.04) 30.28,35.04 v2(29.09,36.23)
  vias: v1(35.9,34.99) v1(37.65,36.21) v1(37.65,34.99) v1(37.65,33.8) v1(44.68,41.67) v1(46.76,41.67)
VH: length 26
  TOP w0.203: v2(28.79,33.41) 29.31,33.93 29.31,34.66 29.45,34.8 U2.B4
  TOP w0.305: v1(17.41,36.27) TP25.1 P3.10
  BOTTOM w0.305: v2(28.79,33.41) 28.31,33.89 27.03,33.89 25.91,32.77 22.99,32.77 22.23,33.53 22.23,35.13 21.08,36.27 v1(17.41,36.27)
VL: length 32.2
  TOP w0.203: U2.A4 v2(29.71,33.16)
  TOP w0.305: v1(19.95,37.54) TP24.1 2.64,37.54 2.36,37.26 P3.9
  BOTTOM w0.305: v1(19.95,37.54) 22.67,37.54 25.2,35.02 28.99,35.02 29.71,34.3 v2(29.71,33.16)
VM+: length 9.2
  TOP w0.305: Q3.5 36.4,38.12 ; Q1.3 35.4,55.6 ; Q5.5 36.4,21.09 ; Q5.3 35.4,21.54 ; Q1.5 36.4,55.15 ; Q3.3 35.4,38.57
  TOP w0.381: TP40.1 v1(15.43,23.7)
  vias: v1(1.34,24.59) v1(2.36,24.59) v1(3.38,24.59) v1(24.19,48.61) v1(24.19,31.58) v1(24.19,14.55) v1(25.02,55.82) v1(25.02,38.79) v1(25.02,21.76) v1(25.65,48.61) v1(25.65,31.58) v1(25.65,14.55) v1(26.42,55.82) v1(26.42,38.79) v1(26.42,21.76) v1(27.11,48.61) v1(27.11,31.58) v1(27.11,14.55) v1(28.57,48.61) v1(28.57,31.58) v1(28.57,14.55) v1(30.04,48.61) v1(30.04,31.58) v1(30.04,14.55) v1(31.5,48.61) v1(31.5,31.58) v1(31.5,14.55) v1(32.26,55.82) v1(32.26,38.79) v1(32.26,21.76) v1(33.66,55.82) v1(33.66,38.79) v1(33.66,21.76) v1(35.18,55.82) v1(35.18,38.79) v1(35.18,21.76) v1(36.58,55.82) v1(36.58,38.79) v1(36.58,21.76) v1(38.1,55.82) v1(38.1,54.68) v1(38.1,38.79) v1(38.1,37.65) v1(38.1,21.76) v1(38.1,20.62) v1(38.73,53.23) v1(38.73,50.94) v1(38.73,48.63) v1(38.73,36.2) v1(38.73,33.91) v1(38.73,31.6) v1(38.73,19.17) v1(38.73,16.88) v1(38.73,14.57) v1(50.69,63.47) v1(50.69,62.2) v1(50.69,60.93) v1(51.96,63.47) v1(51.96,62.2) v1(51.96,60.93) v1(52.7,6.74) v1(52.7,5.47) v1(52.7,4.2) v1(52.7,2.93) v1(53.23,63.47) v1(53.23,62.2) v1(53.23,60.93) v1(54.61,5.47) v1(54.61,4.2) v1(54.61,2.93)
W: length 7
  TOP w0.356: U6.3 45.39,55.43 v1(44.68,56.15)
  TOP w0.508: v1(58.55,41.05) C93.1 v1(59.69,40.06) ; TP30.1 43.18,57.48 R1.1
  vias: v1(44.68,58.69) v1(44.68,57.42)
WH: length 33.2
  TOP w0.203: v2(28.79,50.45) 29.31,50.97 29.31,51.69 29.45,51.83 U1.B4
  TOP w0.305: v1(22.23,49.92) 22.23,41.27 19.76,38.81 TP27.1 P3.12
  BOTTOM w0.305: v1(22.23,49.92) 26.04,49.92 27.03,50.92 28.31,50.92 v2(28.79,50.45)
WL: length 42
  TOP w0.203: U1.A4 v2(29.71,50.19)
  TOP w0.305: P3.11 2.36,39.8 2.64,40.08 8.64,40.08 TP26.1 20.98,42.01 v1(20.98,52.05)
  BOTTOM w0.305: v2(29.71,50.19) 29.71,51.33 28.99,52.05 v1(20.98,52.05)

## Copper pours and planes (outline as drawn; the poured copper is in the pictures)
+5V_VM on TOP (solid shape): 44.92,36.46 46.52,36.46 46.52,38.03 46.87,38.03 46.87,36.46 49.4,36.46 49.4,35.06 46.87,35.06 46.87,32.11 46.52,32.11 46.52,34.68 44.45,34.68 44.45,38.03 44.92,38.03
+5V_VM on TOP: 46.87,55.04 46.52,55.04 46.52,53.48 44.92,53.48 44.92,55.04 44.45,55.04 44.45,51.7 46.52,51.7 46.52,49.12 46.87,49.12 46.87,52.07 49.4,52.07 49.4,53.48 46.87,53.48
+5V_VM on TOP: 28.95,35.12 28.38,35.12 28.2,35.3 24.77,35.3 24.38,35.69 24.38,37.09 24.89,37.59 27.05,37.59 27.43,37.21 28.08,37.21 28.35,36.94 28.35,36.12 28.95,35.52
+5V_VM on TOP: 28.95,52.15 28.38,52.15 28.2,52.33 24.77,52.33 24.38,52.72 24.38,54.12 24.89,54.62 27.05,54.62 27.43,54.24 28.08,54.24 28.35,53.97 28.35,53.15 28.95,52.55
+5V_VM on TOP: 46.87,20.12 46.52,20.12 46.52,18.56 44.92,18.56 44.92,20.12 44.45,20.12 44.45,16.78 46.52,16.78 46.52,14.2 46.87,14.2 46.87,17.15 49.4,17.15 49.4,18.56 46.87,18.56
+5V_VM on TOP: 6.96,41.35 6.96,40.72 8.64,40.72 8.95,40.4 11.3,40.4 11.56,40.65 11.56,42.18 11.3,42.43 9.09,42.43 8.64,41.99 6.96,41.99 6.99,41.96 6.99,41.35
+5V_VM on TOP: 28.95,18.09 28.38,18.09 28.2,18.27 24.77,18.27 24.38,18.66 24.38,20.06 24.89,20.56 27.05,20.56 27.43,20.18 28.08,20.18 28.35,19.91 28.35,19.09 28.95,18.49
+5V_VM on BOTTOM: 8.89,40.65 9.14,40.4 11.18,40.4 11.43,40.65 11.43,42.18 11.18,42.43 9.27,42.43 8.89,42.05
GND on TOP: 1.02,68.5 1.16,68.84 1.5,68.98 68.5,68.98 68.84,68.84 68.98,68.5 68.98,1.5 68.84,1.16 68.5,1.02 1.5,1.02 1.16,1.16 1.02,1.5 ; 3 cut-outs
GND on BOTTOM: 1.02,68.5 1.16,68.84 1.5,68.98 68.5,68.98 68.84,68.84 68.98,68.5 68.98,1.5 68.84,1.16 68.5,1.02 1.5,1.02 1.16,1.16 1.02,1.5 ; 5 cut-outs
GND on L2_GND: 1.02,68.5 1.16,68.84 1.5,68.98 68.5,68.98 68.84,68.84 68.98,68.5 68.98,1.5 68.84,1.16 68.5,1.02 1.5,1.02 1.16,1.16 1.02,1.5 ; 6 cut-outs
(no net) on TOP: 46.87,38.03 46.52,38.03 46.52,36.46 44.92,36.46 44.92,38.03 44.45,38.03 44.45,34.68 46.52,34.68 46.52,32.11 46.87,32.11 46.87,35.06 49.4,35.06 49.4,36.46 46.87,36.46
(no net) on BOTTOM: 36.27,36.7 36.27,35.81 35.58,35.12 35.58,34.86 36.14,34.29 36.14,33.3 37.73,33.3 37.97,33.54 37.97,36.46 37.73,36.7
_N13 on TOP: 30.91,52.33 30.81,52.23 30.91,52.13 31.16,52.13 31.47,51.82 34.06,51.82 34.75,51.13 34.75,49.38 37.05,49.38 37.05,49.78 37.97,50.7 37.97,53.36 37.05,54.28 37.05,54.73 34.75,54.73 34.75,53.06 34.44,52.76 31.44,52.76 31.02,52.33
_N13 on TOP: 29.81,52.63 29.81,52.86 29.36,53.31 29.36,54.15 28.75,54.15 28.75,53.06 29.26,52.55 29.74,52.55
_N13 on TOP: 49.22,55.72 46.66,55.72 46.44,55.93 46.44,58.69 46.44,58.9 46.66,59.12 49.22,59.12
_N13 on BOTTOM: 36.27,53.73 36.27,52.84 35.58,52.15 35.58,51.89 36.14,51.32 36.14,50.33 37.73,50.33 37.97,50.57 37.97,53.49 37.73,53.73
_N13 on L3_SIG: 40.89,59.2 47.75,59.2 47.75,46.75 35.31,46.75 35.31,54.12 40.64,54.12 40.82,54.19 40.89,54.37
_N42 on TOP: 30.89,52.55 30.81,52.63 30.81,52.86 31.19,53.24 31.55,53.24 31.81,53.5 31.81,55.23 34.73,55.23 35.05,54.91 35.05,54.41 35.03,54.38 33.27,54.38 32.89,54 32.89,53.37 32.44,52.91 31.32,52.91 30.96,52.55
_N43 on TOP: 30.91,51.53 30.81,51.43 30.81,50.44 31.45,49.81 33.96,49.81 34.5,50.35 35,50.35 35.05,50.4 35.05,50.65 35,50.7 33.55,50.7 33.43,50.57 31.78,50.57 31.01,51.33 31.01,51.44 30.92,51.53
_N44 on TOP: 30.89,35.52 30.81,35.6 30.81,35.83 31.19,36.21 31.55,36.21 31.81,36.47 31.81,38.2 34.73,38.2 35.05,37.88 35.05,37.38 35.03,37.35 33.27,37.35 32.89,36.97 32.89,36.34 32.44,35.88 31.32,35.88 30.96,35.52
_N45 on TOP: 30.91,34.5 30.81,34.4 30.81,33.41 31.45,32.78 33.96,32.78 34.5,33.32 35,33.32 35.05,33.37 35.05,33.62 35,33.67 33.55,33.67 33.43,33.54 31.78,33.54 31.01,34.3 31.01,34.4 30.92,34.5
_N46 on TOP: 30.89,18.49 30.81,18.57 30.81,18.8 31.19,19.18 31.55,19.18 31.81,19.44 31.81,21.17 34.73,21.17 35.05,20.85 35.05,20.35 35.03,20.32 33.27,20.32 32.89,19.94 32.89,19.31 32.44,18.85 31.32,18.85 30.96,18.49
_N47 on TOP: 30.91,17.47 30.81,17.37 30.81,16.38 31.45,15.75 33.96,15.75 34.5,16.29 35,16.29 35.05,16.34 35.05,16.59 35,16.64 33.55,16.64 33.43,16.51 31.78,16.51 31.01,17.27 31.01,17.37 30.92,17.47
_N48 on TOP: 30.41,52.63 30.41,53.14 30.73,53.47 30.73,55.16 30.81,55.23 31.44,55.23 31.44,53.59 31.32,53.47 31.14,53.47 30.61,52.94 30.61,52.63 30.52,52.53
_N49 on TOP: 30.41,35.6 30.41,36.11 30.73,36.44 30.73,38.13 30.81,38.2 31.44,38.2 31.44,36.56 31.32,36.44 31.14,36.44 30.61,35.91 30.61,35.6 30.52,35.5
_N50 on TOP: 30.41,18.57 30.41,19.08 30.73,19.41 30.73,21.1 30.81,21.17 31.44,21.17 31.44,19.53 31.32,19.41 31.14,19.41 30.61,18.88 30.61,18.57 30.52,18.47
_N68 on TOP: 32.45,51.57 33.41,51.57 33.41,50.93 31.67,50.93 30.81,51.79 30.81,51.87 30.89,51.94 31.22,51.94 31.6,51.56 32.44,51.56
_N70 on TOP: 32.45,17.51 33.41,17.51 33.41,16.87 31.67,16.87 30.81,17.73 30.81,17.81 30.89,17.88 31.22,17.88 31.6,17.5 32.44,17.5
_N71 on TOP: 32.45,34.54 33.41,34.54 33.41,33.9 31.67,33.9 30.81,34.76 30.81,34.84 30.89,34.91 31.22,34.91 31.6,34.53 32.44,34.53
_N135 on BOTTOM: 63.5,8.82 63.5,14.36 43.81,14.36 43.81,10.55 40.16,10.55 40.16,2.3 43.81,2.3 43.81,6.11 48.9,6.11 48.9,8.82
_N140 on TOP: 67.31,61.35 63.5,61.35 62.23,60.08 62.23,48.02 62.87,47.38 67.94,47.38 68.96,48.4 68.96,59.71
U on TOP: 42.22,20.79 44.78,20.79 45,21.01 45,23.76 45,23.98 44.78,24.19 42.22,24.19
U on BOTTOM: 51.44,25.79 43.81,25.79 43.81,18.81 55.88,18.81 55.88,27.7 65.41,27.7 65.41,31.51 51.44,31.51
U_X on TOP: 30.91,18.27 30.81,18.17 30.91,18.07 31.16,18.07 31.47,17.76 34.06,17.76 34.75,17.07 34.75,15.32 37.05,15.32 37.05,15.72 37.97,16.64 37.97,19.3 37.05,20.22 37.05,20.67 35.33,20.67 35.33,20.14 34.75,20.14 34.75,19 34.44,18.7 31.44,18.7 31.02,18.27
U_X on TOP: 29.81,18.57 29.81,18.8 29.36,19.25 29.36,20.09 28.75,20.09 28.75,19 29.26,18.49 29.74,18.49
U_X on TOP: 49.22,20.79 46.66,20.79 46.44,21.01 46.44,23.76 46.44,23.98 46.66,24.19 49.22,24.19
U_X on BOTTOM: 36.27,19.67 36.27,18.77 35.58,18.09 35.58,17.83 36.14,17.26 36.14,16.27 37.73,16.27 37.97,16.51 37.97,19.43 37.73,19.67
U_X on L3_SIG: 40.89,25.14 47.75,25.14 47.75,12.69 35.31,12.69 35.31,20.06 40.64,20.06 40.82,20.13 40.89,20.31
V on BOTTOM (solid shape): 37.97,36.46 37.97,33.54 37.73,33.3 36.14,33.3 36.14,34.29 35.58,34.86 35.58,35.12 36.27,35.81 36.27,36.7 37.73,36.7
V on TOP: 29.81,35.6 29.81,35.83 29.36,36.28 29.36,37.12 28.75,37.12 28.75,36.03 29.26,35.52 29.74,35.52
V on TOP: 49.22,38.7 46.66,38.7 46.44,38.91 46.44,41.67 46.44,41.89 46.66,42.1 49.22,42.1
V on TOP: 30.91,35.3 30.81,35.2 30.91,35.1 31.16,35.1 31.47,34.79 34.06,34.79 34.75,34.1 34.75,32.35 37.05,32.35 37.05,32.75 37.97,33.67 37.97,36.33 37.05,37.25 37.05,37.7 35.69,37.7 35.69,37.15 34.75,37.15 34.75,36.03 34.44,35.73 31.44,35.73 31.02,35.3
V on TOP: 42.22,38.7 44.78,38.7 45,38.91 45,41.67 45,41.89 44.78,42.1 42.22,42.1
V on BOTTOM: 51.44,33.41 65.41,33.41 65.41,36.59 55.88,36.59 55.88,46.11 42.55,46.11 42.55,38.49 45.72,38.49 45.72,42.94 51.44,42.94
V on L3_SIG: 45.12,41.97 44.87,42.17 47.75,42.17 47.75,29.72 35.31,29.72 35.31,37.09 40.64,37.09 40.82,37.16 40.89,37.34 40.89,42.17 44.48,42.17 44.24,41.97 44.15,41.67 44.68,41.14 45.21,41.67 ; 2 cut-outs
VM+ on TOP: 41.57,23.24 24.35,23.24 24.35,21.5 24.89,20.96 37.33,20.96 38.48,19.8 38.48,14.35 38.16,14.03 32.71,14.03 31.51,15.23 24.13,15.23 23.5,14.59 23.5,13.32 23.86,12.96 41.57,12.96 41.57,14.06 41.4,14.23 40.26,14.23 40.15,14.33 40.15,21.87 40.26,21.97 41.4,21.97 41.57,22.14
VM+ on TOP: 41.57,40.27 24.35,40.27 24.35,38.53 24.89,37.99 37.33,37.99 38.48,36.83 38.48,31.38 38.16,31.06 32.57,31.06 31.37,32.26 24.13,32.26 23.5,31.62 23.5,30.35 23.86,29.99 41.57,29.99 41.57,31.09 41.4,31.26 40.26,31.26 40.15,31.36 40.15,38.9 40.26,39 41.4,39 41.57,39.17
VM+ on TOP: 41.57,57.3 24.35,57.3 24.35,55.56 24.89,55.02 37.33,55.02 38.48,53.86 38.48,48.41 38.16,48.09 32.56,48.09 31.36,49.29 24.13,49.29 23.5,48.65 23.5,47.38 23.86,47.02 41.57,47.02 41.57,48.12 41.4,48.29 40.26,48.29 40.15,48.39 40.15,55.93 40.26,56.03 41.4,56.03 41.57,56.2
VM+ on TOP: 1.33,26.75 3.2,26.75 3.81,26.13 3.81,24.14 3.56,23.89 1.27,23.89 1.02,24.14 1.02,26.43
VM+ on TOP: 50.16,48.02 50.8,47.38 55.24,47.38 55.88,48.02 55.88,55 54.61,56.27 54.61,63.89 53.98,64.53 50.8,64.53 50.16,63.89
VM+ on BOTTOM: 40.15,31.51 40.15,39.1 39.62,39.63 31.62,39.63 31.37,39.37 31.37,38.61 31.62,38.36 36.02,38.36 36.14,38.23 36.14,37.24 38.08,37.24 38.48,36.83 38.48,31.5 38.61,31.37 40.02,31.37
VM+ on BOTTOM: 40.15,48.54 40.15,56.13 39.62,56.66 31.62,56.66 31.37,56.4 31.37,55.64 31.62,55.39 36.02,55.39 36.14,55.26 36.14,54.27 38.08,54.27 38.48,53.86 38.48,48.53 38.61,48.4 40.02,48.4
VM+ on BOTTOM: 63.5,7.21 63.5,1.03 51.44,1.03 51.44,7.21
VM+ on BOTTOM: 40.15,14.48 40.15,22.07 39.62,22.6 31.62,22.6 31.37,22.34 31.37,21.58 31.62,21.33 36.02,21.33 36.14,21.2 36.14,20.21 38.08,20.21 38.48,19.8 38.48,14.47 38.61,14.34 40.02,14.34
VM+ on L3_SIG: 1.02,68.5 1.16,68.84 1.5,68.98 68.5,68.98 68.84,68.84 68.98,68.5 68.98,1.5 68.84,1.16 68.5,1.02 1.5,1.02 1.16,1.16 1.02,1.5 ; 4 cut-outs
W on TOP: 42.22,55.72 44.78,55.72 45,55.93 45,58.69 45,58.9 44.78,59.12 42.22,59.12
W on BOTTOM: 57.15,54.37 57.15,37.86 65.41,37.86 65.41,43.57 60.96,43.57 60.96,59.45 42.55,59.45 42.55,54.37

Small or netless copper shapes (teardrops, artwork), in the pictures only: 3 on TOP

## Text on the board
BOTTOM: 08-087967A | SECONDARY SIDE
TOP: 08-087967A | PRIMARY SIDE
Ref Des/Silkscreen Top: ADCIV | +5V_VM | ADCIW | BRAKE | VM+ | WH | VH | UH | ADCIU | UN1 | WL | VL | UL | GND | V | U | W- | V- | U- | W+ | V+ | U+ | 125V (DC) | 16AMP | 1 | 2 | 4 | 3 | CAUTION | HIGH VOLTAGE | U,V,W | BST | TG | BG | A | LT8418 EVAL-1 Z | C | B | W | BRIDGE BOARD
DIMENSION: FAB NOTES REVISION: NOVEMBER 21 2022 | 8.   IMPEDANCE REQUIREMENTS: IF NO STACKUP IS DEFINED, THE VENDOR IS ALLOWED TO ADJUST THE DIELECTRIC | 13.  PLATING SPECIFICATION: | 9.   FILLET OPTIONS TO ENHANCE RELIABILITY AT PAD JUNCTIONS WHERE SPACING PERMITS. | 10.  THIEVING: | 11.  LAYER TO LAYER REGISTRATION SHALL BE WITHIN 0.003 INCHES. | 12.  DRILL SIZES ARE FINISHED HOLE SIZES. ALL HOLES SHALL BE LOCATED WITHIN 0.005 INCHES DTP,UNLESS SPECIFIED. | 14.  SURFACE FINISH: | 15.  SOLDERMASK: | 1.   DIMENSIONS ARE IN INCHES (EXCEPT WHERE NOTED). | ALL DOCUMENTS & SPECIFICATIONS REFERRED TO BELOW SHOULD BE THE LATEST REVISIONS. | 2.  BOARD MATERIAL:(USE CHECKED ITEMS) | 3.   ALL LAMINATES & BONDING MATERIALS SHOULD BE SELECTED FROM IPC-4101 OR IPC-4103,(TG>170 DEGC TD>300 DEGC) | 4.   REFER TO IPC-6010 SERIES, CLASS 2 FOR FABRICATION. | 5.   REFER TO LAMINATION DIAGRAM FOR OVERALL BOARD THICKNESS, TOLERANCE APPLIES AFTER ALL LAMINATION AND PLATING | 6.   BOW & TWIST NOT TO EXCEED 0.0075 INCHES (0.75%) PER LINEAR INCH AND SHOULD BE MEASURED PER IPC-TM-650, METHOD 2.4.22. | 7.   ACCEPTABILITY PER ADI SPECIFICATION TST00115. | 16.  APPLY SILKSCREEN TO BOTH SIDES USING A NON-CONDUCTIVE, EPOXY BASED INK PER ARTWORK. | ( ) FILLETS ALLOWED | (X) FILLETS NOT ALLOWED | ( ) VENDOR MAY ADD THIEVING TO COMPENSATE FOR LOW COPPER DENSITY AREAS MAINTAINING A MINIMUM | ( ) VENDOR MAY NOT ADD THIEVING TO COMPENSATE FOR LOW COPPER DENSITY AREAS. | (X) LPI | ( ) OTHER_________ | COLOR | ( ) GREEN | (X) OTHER: WHITE | ( ) WHITE | (X) OTHER: BLACK | HINDER PROPER SOLDER WICKING. BARREL RELIEF ON SOLDERMASK ALLOWED IN UNFILLED VIA IN PAD HOLES. | (X) REFER TO LAMINATION DIAGRAM FOR FINISHED COPPER WEIGHT/THICKNESS REQUIRMENTS | (X) IMMERSION GOLD (ENIG) 1.58-3.94 MICRO INCHES OVER 118-236 MICRO INCHES MIN. OF ELECTROLESS NICKEL PER IPC-4552 | ( ) OSP (ORGANIC SOLDERABILITY PRESERVATIVE) | ( ) IMMERSION SILVER | ( ) SOFT WIRE BONDABLE GOLD 30-50 MICRO INCHES OF SOFT WIRE | ( ) EDGE CONNECTOR FINGERS ARE TO BE PLATED WITH 100 MICRO-INCHES(.0001") OF LOW STRESS | THICKNESS & TRACE WIDTHS TO MEET THE IMPEDANCE REQUIREMENT. IF SPECIFIED, THE VENDOR MUST | TRACE WIDTH & SPACING THAT IMPACT THE REQUIREMENTS MUST HAVE WRITTEN APPROVAL FROM ADI. | MINIMUM BARREL PLATING OF 0.001 INCHES. PLATED HOLES SHALL NOT BE ROUGH OR IRREGULAR SO AS TO | SOLDERMASK OVER BARE COPPER OR BARE GOLD (BOTH SIDES) TO MEET IPC-SM-840. | IF PRESENT,DO NOT MODIFY SOLDERMASK DEFINED PADS (MASK OPENINGS LESS THAN COPPER PAD) WITHOUT APPROVAL. | MEET THE REQUIREMENTS LISTED IN THE IMPEDANCE TABLE. ANY ADJUSTMENT MADE TO THE DEFINED STACKUP, | PROCESSES. FINISHED THICKNESS MEASURED FROM TOP COPPER TO BOTTOM COPPER. | (X)  ISOLA 370HR OR S1000-2 OR IT180 OR EQUIVALENT | ( )  ISOLA-FR408HR OR EQUIVALENT | ( )  ISOLA IS410 | ( )  MEGTRON 6 | ( )  NELCO-4000-13 | ( )  ROGERS 4350B | ( ) ROGERS 3003 | ( ) ARLON 85N | ( ) EM370D | ( )  OTHER ________________________ | UL FLAMMABILITY RATING 94V-0. BOARD MATERIAL & CONSTRUCTION SHALL MEET THE REQUIREMENTS OF UL796/UL796F. | BONDABLE GOLD OVER 100-150 MICRO INCHES OF NICKEL | NICKEL UNDER 30 MICRO-INCHES (.00003') OF GOLD | 0.100 INCH CLEARANCE FROM ALL COPPER FEATURES, | THE STARTING COPPER WEIGHT/THICKNESS CAN VARY AS LONG AS THE FINISHED COPPER | WEIGHT/THICKNESS IS NOT LESS THAN THE SPECIFIED VALUE. | UNLESS OTHERWISE SPECIFIED | HOMOGENOUS MATERIALS IN THIS BOARD SHALL BE COMPLAINT WITH THE EU DIRECTIVE 2002/95/EC | WORKMANSHIP SHALL CONFORM TO IPC-A-600, CLASS 2. | 21.  INTENTIONAL SHORTS: | 17.  FINAL ELECTRICAL TEST TO BE PERFORMED USING PROVIDED IPC-D-356A NETLIST OR ODB++ FORMAT FILE. | 22.  PEMNUTS: | 23.  MANUFACTURER TO ETCH/STAMP WITH PERMANENT NON-CONDUCTIVE INK | ON SECONDARY SIDE UNLESS OTHERWISE SPECIFIED: | 18.  A TIME DOMAIN REFLECTOMETER REPORT (TDR) FOR EACH IMPEDANCE CONTROLLED LAYER & A CERTIFICATE | 19.  IF PRESENT, ALL BLIND/BURIED VIAS WITH AN ASPECT RATIO <1:1 TO BE PLATED SHUT WITH COPPER WHEN | 20.  FOR VIA FILL INFORMATION REFER TO DRILL CHART: | 25. PANELIZATION: | 27.  MINIMUM DESIGN LINE WIDTH IS 0.2032 MM. | 28.  MINIMUM DESIGN LINE SPACING IS 0.127 MM. | IS ACCEPTABLE, ALL OTHER INSTANCES MUST BE REPORTED. | IF AN INTENTIONAL SHORT REPORT IS SUPPLIED AND DOES NOT MATCH THE FAB DATA THEN | THE PCB SHALL HAVE A VERIFICATION STAMP. | ( )  NON-CONDUCTIVE EPOXY FILL ALL 0.XXXX INCHES DRILLED VIAS | ( )  COPPER FILL ALL 0.XXXX INCHES DRILLED VIAS | ( ) PEMNUTS TO BE INSTALLED BY FABRICATOR | ( ) PEMNUTS NOT TO BE INSTALLED BY FABRICATOR | ( ) NOT APPLICABLE | USED AS VIA-IN-PAD OR AS A STACKED VIA. BLIND/BURIED VIAS WITH AN ASPECT RATIO >1:1 TO BE FILLED | A. UL CODE-FLAMMABILITY RATING FOR THOSE APPROVED MATERIALS(IF APPLICABLE) | B. DATE CODE | C. LOT NUMBER | D. MANUFACTURER LOGO | BOARDS TO BE SHIPPED SINGULATED AFTER FABRICATION PROCESS. | SMOOTHEN EDGES AND FREE FROM BURRS AFTER DEPANELIZATION PROCESS. | CAN'T BE PERFORMED BECAUSE THE TRACE LENGTH IS TOO SHORT ON THE OUTER LAYERS AT THE PIN ESCAPES | ADI APPROVAL IS REQUIRED. | OF COMPLIANCE SHALL BE PROVIDED BY VENDOR AT TIME OF SHIPMENT. INSTANCES WHERE TDR TESTING | WITH NON-CONDUCTIVE EPOXY. | TOOLING: | FINISH: | NOTES: | MATERIAL: | TESTING: | MISCELLANEOUS: | REF | DIA MAX
DISPLAY_TOP: LABEL PLACEMENT INFORMATION | HALF SIZE LABELS ARE | AVAILABLE IN THE LIBRARY | PLACE WHEELIE BIN LOGO | TO SUIT THE LAYOUT. | PLACE ROHS COMPLIANT LOGO | TO SUIT THE LAYOUT OR | DELETE IF NOT REQ'D. | PLACE CHINA ROHS COMPLIANT | LOGO TO SUIT THE LAYOUT OR | 1.THE BOARD SIZE CAN BE ADJUSTED TO SUIT THE APPLICATION. | 2.THE MOUNTING HOLES CAN BE MOVED/REMOVED TO SUIT THE APPLICATION. | 3.THE FIDUCIALS CAN BE MOVED TO SUIT THE APPLICATION. | 4.ADJUST THE DIMENSIONS TO SUIT THE APPLICATION. | 5.ADD THE CORRECT LAYER STACKUP ON FAB2 BASED ON THE NO OF LAYERS ON THE PCB. | 6.THE ROHS COMPLIANT AND WHEELIE BIN LOGO'S CAN BE MOVED TO THE DESIRED LOCATION. | HALF SIZE VERSIONS OF THE LABELS ARE AVAILABLE IN THE LIBRARY. | NOTES FOR TEMPLATE USAGE.
User.17: L2 GND | 08-      -07
User.18: L3 SIG | 08-      -08
User.45: FIGURE | SIZE | 0.2032 | 0.3048 | 0.5588 | 1.524 | 0.9652 | 1.397 | 1.6002 | 1.778 | 3.175 | PLATED | NON-PLATED | DRILL CHART: TOP to BOTTOM | ALL UNITS ARE IN MILLIMETERS | QTY | 28 | 352 | 3 | 7 | 16 | 1 | 2 | 4 | 414 | TOLERANCE/NOTES | TOTAL HOLES:
